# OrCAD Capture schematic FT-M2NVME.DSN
size A3; title: FT.F-NVMEM2; rev: 1.0
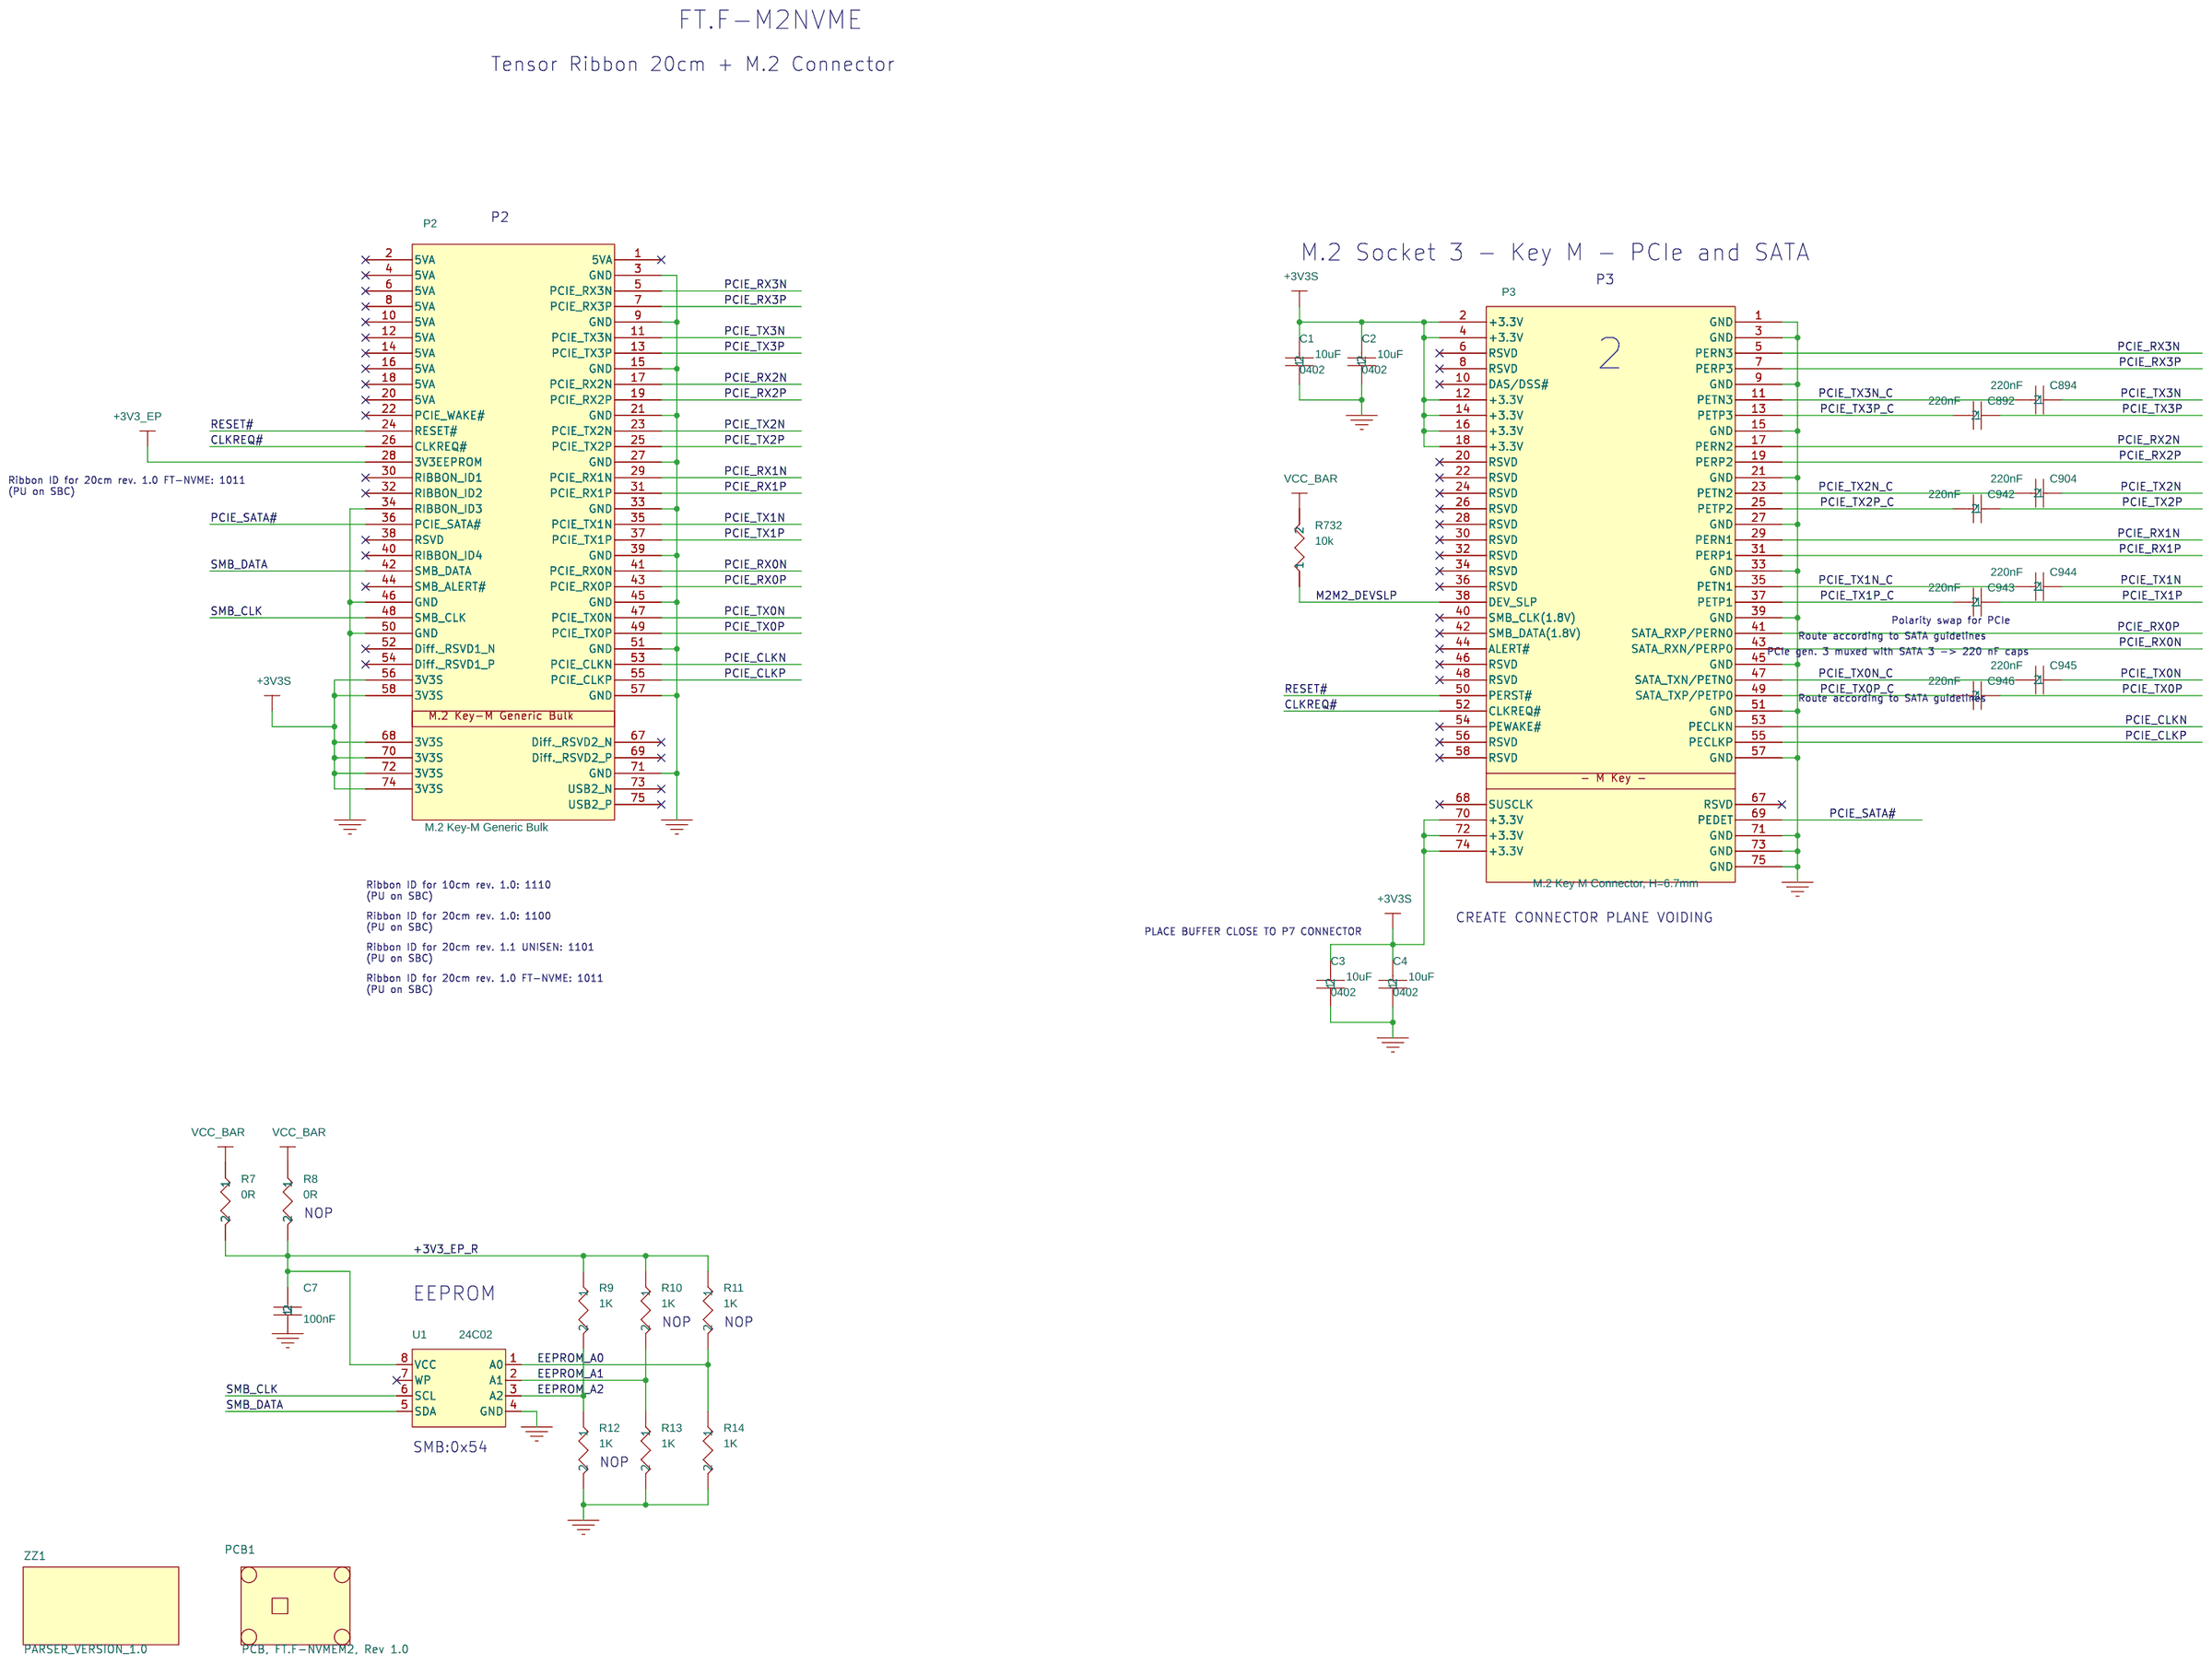
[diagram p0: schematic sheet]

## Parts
C1  10uF  [0402]
C2  10uF  [0402]
C3  10uF  [0402]
C4  10uF  [0402]
C7  100nF  [RC0402]
C892  220nF  [RC0402]
C894  220nF  [RC0402]
C904  220nF  [RC0402]
C942  220nF  [RC0402]
C943  220nF  [RC0402]
C944  220nF  [RC0402]
C945  220nF  [RC0402]
C946  220nF  [RC0402]
P2  M.2 Key-M Generic Bulk  [EdgeM2keyM]
P3  M.2 Key M Connector, H=6.7mm  [QFN4x4-32]
PCB1  PCB, FT.F-NVMEM2, Rev 1.0
R7  0R  [RC0402]
R8  0R  [RC0402]
R9  1K  [RC0402]
R10  1K  [RC0402]
R11  1K  [RC0402]
R12  1K  [RC0402]
R13  1K  [RC0402]
R14  1K  [RC0402]
R732  10k  [RC0402]
U1  24C02  [MO-229VCED-2]
ZZ1  PARSER_VERSION_1.0

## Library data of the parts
C1 = 100nF,_10V,_X7R,_10%,_0402_7: CLABCONF0: FT.F-M2NVME; P/N: 151B10600S
C2 = 100nF,_10V,_X7R,_10%,_0402_6: CLABCONF0: FT.F-M2NVME; P/N: 151B10600S
C3 = 100nF,_10V,_X7R,_10%,_0402_1: CLABCONF0: FT.F-M2NVME; P/N: 151B10600S
C4 = 100nF,_10V,_X7R,_10%,_0402: CLABCONF0: FT.F-M2NVME; P/N: 151B10600S
C7 = 15pF,_50V,_NPO,_5%,_0402: CLABCONF0: FT.F-M2NVME; P/N: 151B10400S
C892 = 100nF,_10V,_X7R,_10%,_0402_8: CLABCONF0: FT.F-M2NVME; P/N: 151C22400S
C894 = 100nF,_10V,_X7R,_10%,_0402_9: CLABCONF0: FT.F-M2NVME; P/N: 151C22400S
C904 = 100nF,_10V,_X7R,_10%,_0402_5: CLABCONF0: FT.F-M2NVME; P/N: 151C22400S
C942 = 100nF,_10V,_X7R,_10%,_0402_4: CLABCONF0: FT.F-M2NVME; P/N: 151C22400S
C943 = 100nF,_10V,_X7R,_10%,_0402_3: CLABCONF0: FT.F-M2NVME; P/N: 151C22400S
C944 = 100nF,_10V,_X7R,_10%,_0402_2: CLABCONF0: FT.F-M2NVME; P/N: 151C22400S
C945 = 100nF,_10V,_X7R,_10%,_0402_10: CLABCONF0: FT.F-M2NVME; P/N: 151C22400S
C946 = 100nF,_10V,_X7R,_10%,_0402_11: CLABCONF0: FT.F-M2NVME; P/N: 151C22400S
P2 = M.2_Key-M_Generic_Bulk: CLABCONF0: FT.F-M2NVME; P/N: NA1
P3 = M.2_Key_M_Connector: CLABCONF0: FT.F-M2NVME; P/N: 182K06706S
PCB1 = SBC-iHSW_Rev_1.0: CLABCONF0: FT.F-M2NVME; P/N: 188C03380
R7 = 348R,1%,0402,1_16W_6: CLABCONF0: FT.F-M2NVME; P/N: 161C00005S
R8 = 348R,1%,0402,1_16W_3: CLABCONF0: NOP; P/N: 161C00005S
R9 = 348R,1%,0402,1_16W: CLABCONF0: FT.F-M2NVME; P/N: 161C10011S
R10 = 348R,1%,0402,1_16W_4: CLABCONF0: NOP; P/N: 161C10011S
R11 = 348R,1%,0402,1_16W_2: CLABCONF0: NOP; P/N: 161C10011S
R12 = 348R,1%,0402,1_16W_7: CLABCONF0: NOP; P/N: 161C10011S
R13 = 348R,1%,0402,1_16W_1: CLABCONF0: FT.F-M2NVME; P/N: 161C10011S
R14 = 348R,1%,0402,1_16W_5: CLABCONF0: FT.F-M2NVME; P/N: 161C10011S
R732 = 1M_,5%,_0402: CLABCONF0: FT.F-M2NVME; P/N: 161C10021S
U1 = 24C02,_serial_EE,_2KB,_I2C: CLABCONF0: FT.F-M2NVME; P/N: 111S30801S
ZZ1 = PARSER_VERSION_1.0: CLABCONF0: FT.F-M2NVME

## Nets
+3V3_EP: P2.28(3V3EEPROM) R7.1
+3V3_EP_R: C7.2 R7.2 R8.2 R9.1 R10.1 R11.1 U1.8(VCC)
+3V3S: C1.2 C2.2 C3.2 C4.2 P2.56(3V3S) P2.58(3V3S) P2.68(3V3S) P2.70(3V3S) P2.72(3V3S) P2.74(3V3S) P3.2(+3.3V) P3.4(+3.3V) P3.12(+3.3V) P3.14(+3.3V) P3.16(+3.3V) P3.18(+3.3V) P3.70(+3.3V) P3.72(+3.3V) P3.74(+3.3V) R8.1 R732.2
GND: C1.1 C2.1 C3.1 C4.1 C7.1 P2.3(GND) P2.9(GND) P2.15(GND) P2.21(GND) P2.27(GND) P2.33(GND) P2.34(RIBBON_ID3) P2.39(GND) P2.45(GND) P2.46(GND) P2.50(GND) P2.51(GND) P2.57(GND) P2.71(GND) P3.1(GND) P3.3(GND) P3.9(GND) P3.15(GND) P3.21(GND) P3.27(GND) P3.33(GND) P3.39(GND) P3.45(GND) P3.51(GND) P3.57(GND) P3.71(GND) P3.73(GND) P3.75(GND) R12.2 R13.2 R14.2 U1.4(GND)
CLKREQ#: P2.26(CLKREQ#) P3.52(CLKREQ#)
EEPROM_A0: R11.2 R14.1 U1.1(A0)
EEPROM_A1: R10.2 R13.1 U1.2(A1)
EEPROM_A2: R9.2 R12.1 U1.3(A2)
M2M2_DEVSLP: P3.38(DEV_SLP) R732.1
PCIE_CLKN: P2.53(PCIE_CLKN) P3.53(PECLKN)
PCIE_CLKP: P2.55(PCIE_CLKP) P3.55(PECLKP)
PCIE_RX0N: P2.41(PCIE_RX0N) P3.43(SATA_RXN/PERP0)
PCIE_RX0P: P2.43(PCIE_RX0P) P3.41(SATA_RXP/PERN0)
PCIE_RX1N: P2.29(PCIE_RX1N) P3.29(PERN1)
PCIE_RX1P: P2.31(PCIE_RX1P) P3.31(PERP1)
PCIE_RX2N: P2.17(PCIE_RX2N) P3.17(PERN2)
PCIE_RX2P: P2.19(PCIE_RX2P) P3.19(PERP2)
PCIE_RX3N: P2.5(PCIE_RX3N) P3.5(PERN3)
PCIE_RX3P: P2.7(PCIE_RX3P) P3.7(PERP3)
PCIE_SATA#: P2.36(PCIE_SATA#) P3.69(PEDET)
PCIE_TX0N: C945.1 P2.47(PCIE_TX0N)
PCIE_TX0N_C: C945.2 P3.47(SATA_TXN/PETN0)
PCIE_TX0P: C946.1 P2.49(PCIE_TX0P)
PCIE_TX0P_C: C946.2 P3.49(SATA_TXP/PETP0)
PCIE_TX1N: C944.1 P2.35(PCIE_TX1N)
PCIE_TX1N_C: C944.2 P3.35(PETN1)
PCIE_TX1P: C943.1 P2.37(PCIE_TX1P)
PCIE_TX1P_C: C943.2 P3.37(PETP1)
PCIE_TX2N: C904.1 P2.23(PCIE_TX2N)
PCIE_TX2N_C: C904.2 P3.23(PETN2)
PCIE_TX2P: C942.1 P2.25(PCIE_TX2P)
PCIE_TX2P_C: C942.2 P3.25(PETP2)
PCIE_TX3N: C894.1 P2.11(PCIE_TX3N)
PCIE_TX3N_C: C894.2 P3.11(PETN3)
PCIE_TX3P: C892.1 P2.13(PCIE_TX3P)
PCIE_TX3P_C: C892.2 P3.13(PETP3)
RESET#: P2.24(RESET#) P3.50(PERST#)
SMB_CLK: P2.48(SMB_CLK) U1.6(SCL)
SMB_DATA: P2.42(SMB_DATA) U1.5(SDA)

Not connected (* = marked no-connect by the designer): P2 1(5VA)* 2(5VA)* 4(5VA)* 6(5VA)* 8(5VA)* 10(5VA)* 12(5VA)* 14(5VA)* 16(5VA)* 18(5VA)* 20(5VA)* 22(PCIE_WAKE#)* 30(RIBBON_ID1)* 32(RIBBON_ID2)* 38(RSVD)* 40(RIBBON_ID4)* 44(SMB_ALERT#)* 52(Diff._RSVD1_N)* 54(Diff._RSVD1_P)* 67(Diff._RSVD2_N)* 69(Diff._RSVD2_P)* 73(USB2_N)* 75(USB2_P)*; P3 6(RSVD)* 8(RSVD)* 10(DAS/DSS#)* 20(RSVD)* 22(RSVD)* 24(RSVD)* 26(RSVD)* 28(RSVD)* 30(RSVD)* 32(RSVD)* 34(RSVD)* 36(RSVD)* 40(SMB_CLK(1.8V))* 42(SMB_DATA(1.8V))* 44(ALERT#)* 46(RSVD)* 48(RSVD)* 54(PEWAKE#)* 56(RSVD)* 58(RSVD)* 67(RSVD)* 68(SUSCLK)*; U1 7(WP)*

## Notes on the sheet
- FT.F-M2NVME
- Tensor Ribbon 20cm + M.2 Connector
- P2
- M.2 Socket 3 - Key M - PCIe and SATA
- P3
- 2
- Ribbon ID for 20cm rev. 1.0 FT-NVME: 1011
  (PU on SBC)
- Polarity swap for PCIe
- Route according to SATA guidelines
- PCIe gen. 3 muxed with SATA 3 -> 220 nF caps
- Route according to SATA guidelines
- Ribbon ID for 10cm rev. 1.0: 1110
  (PU on SBC)
- Ribbon ID for 20cm rev. 1.0: 1100
  (PU on SBC)
- CREATE CONNECTOR PLANE VOIDING
- PLACE BUFFER CLOSE TO P7 CONNECTOR
- Ribbon ID for 20cm rev. 1.1 UNISEN: 1101
  (PU on SBC)
- Ribbon ID for 20cm rev. 1.0 FT-NVME: 1011
  (PU on SBC)
- NOP
- EEPROM
- NOP
- NOP
- SMB:0x54
- NOP
